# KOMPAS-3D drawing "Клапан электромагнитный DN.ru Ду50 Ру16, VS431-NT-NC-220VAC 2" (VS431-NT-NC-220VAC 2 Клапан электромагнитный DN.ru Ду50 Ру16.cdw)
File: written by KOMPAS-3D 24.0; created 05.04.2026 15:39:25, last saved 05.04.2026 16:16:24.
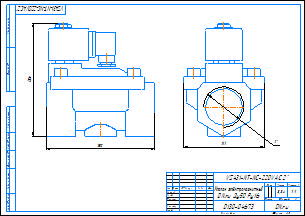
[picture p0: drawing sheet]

Document properties: c3d_UniqueCompID: ef56311e-7521-43dc-8291-0e6108b3d81d; Автор: artio; Класс точности: c; Знак неуказанной шероховатости: Шероховатость не задана; Рассекать на разрезах: Да; c3d_UniqueCompID: ef56311e-7521-43dc-8291-0e6108b3d81d; Автор: artio; Класс точности: c; Знак неуказанной шероховатости: Шероховатость не задана; Рассекать на разрезах: Да; c3d_UniqueCompID: ef56311e-7521-43dc-8291-0e6108b3d81d; Автор: artio; Класс точности: c; Знак неуказанной шероховатости: Шероховатость не задана; Рассекать на разрезах: Да; c3d_UniqueCompID: ef56311e-7521-43dc-8291-0e6108b3d81d; Автор: artio; Класс точности: c; Знак неуказанной шероховатости: Шероховатость не задана; Рассекать на разрезах: Да; c3d_UniqueCompID: ef56311e-7521-43dc-8291-0e6108b3d81d; Автор: artio; Класс точности: c; Знак неуказанной шероховатости: Шероховатость не задана; Рассекать на разрезах: Да; Автор: artio; Форматы листов документа: A3; Полное имя файла: VS431-NT-NC-220VAC 2 Клапан электромагнитный DN.ru Ду50 Ру16.m3d; Масса: 3.341; Наименование: Клапан электромагнитный DN.ru Ду50 Ру16; Количество листов документа: 1; Примечание: D130-04673

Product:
- Body: Тело 1  | qty 1
    Масса: 6.703651
- Part/product: Клапан электромагнитный DN.ru Ду50 Ру16  | designation VS431-NT-NC-220VAC 2
    Масса: 3.341
    Раздел спецификации: Прочие изделия
    Примечание: D130-04673
    additional columns: ef56311e-7521-43dc-8291-0e6108b3d81d; artio; c; Шероховатость не задана; Да

Views: Вид 1, Спереди
Referenced files in C:\Users\artio\OneDrive\Рабочий стол\Клапан электромагнитный DN.ru\VS431\VS431-ET-NC\: VS431-ET-NC-220VAC 3-4 Клапан электромагнитный DN.ru Ду20 Ру16.m3d, VS431-ET-NC-220VAC 3-4 Клапан электромагнитный DN.ru Ду20 Ру16.cdw
Referenced files in C:\Users\artio\OneDrive\Рабочий стол\Клапан электромагнитный DN.ru\VS431\VS431-NT-NC\: VS431-NT-NC-220VAC 2 Клапан электромагнитный DN.ru Ду50 Ру16.m3d
Referenced files in C:\Users\artio\OneDrive\Рабочий стол\Клапан электромагнитный DN.ru\VS431\VS431-NT-NC\VS431-NT-NC-220VAC\Ду50\: VS431-NT-NC-220VAC 2 Клапан электромагнитный DN.ru Ду50 Ру16.m3d
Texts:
  VS431-NT-NC-220VAC 2
  Клапан электромагнитный
  DN.ru Ду50 Ру16
  VS431-NT-NC-220VAC 2"
  VS431-NT-NC-220VAC 2"-
  Клапан электромагнитный DN.ru Ду50 Ру16
  VS431-NT-NC-220VAC 2 Клапан электромагнитный DN.ru Ду50 Ру16
Dimensions and other numbers on the sheet: 0; 3; 2; 4; 111; 1:1; 1; 3,34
